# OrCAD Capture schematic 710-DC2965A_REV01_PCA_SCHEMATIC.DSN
size Custom
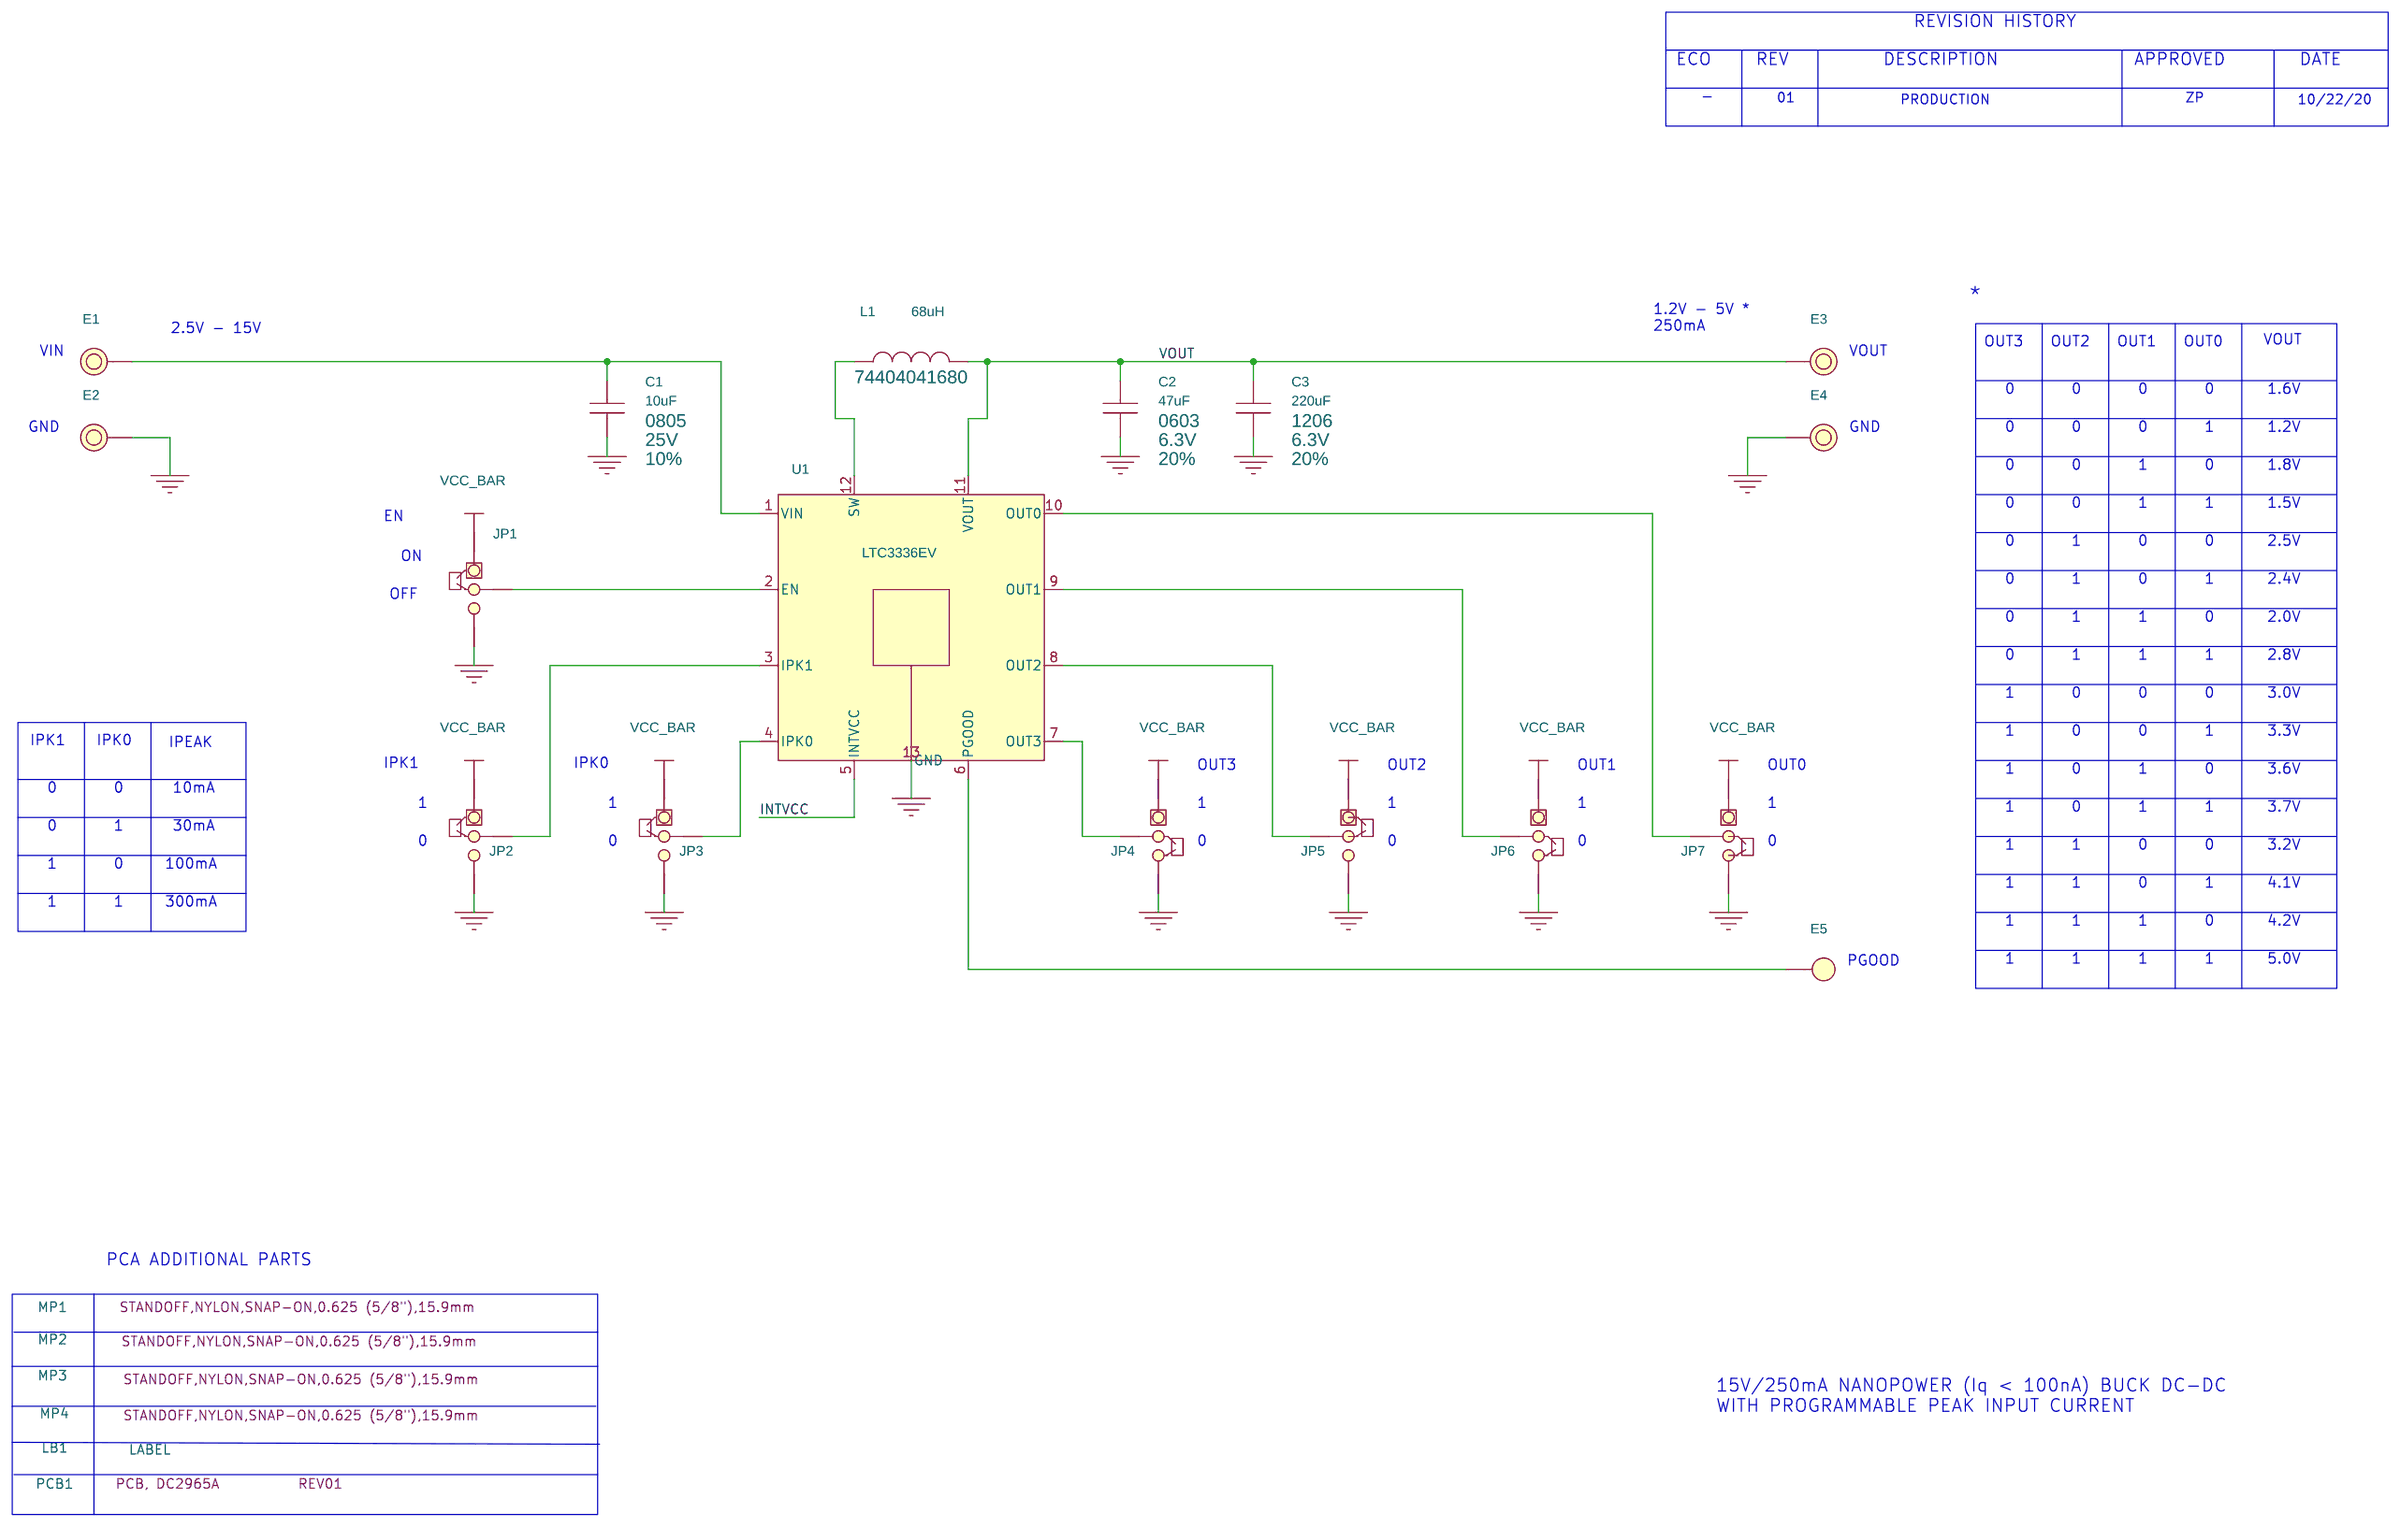
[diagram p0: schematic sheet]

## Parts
C1  10uF  [CC0805N]
C2  47uF  [CC0603N]
C3  220uF  [CC1206N]
E1  TEST POINT  [MILLMAX2501]
E2  TEST POINT  [MILLMAX2501]
E3  TEST POINT  [MILLMAX2501]
E4  TEST POINT  [MILLMAX2501]
E5  TEST POINT  [MILLMAX2308]
JP1  HDR  [HD1X3-079]
JP2  HDR  [HD1X3-079]
JP3  HDR  [HD1X3-079]
JP4  HDR  [HD1X3-079]
JP5  HDR  [HD1X3-079]
JP6  HDR  [HD1X3-079]
JP7  HDR  [HD1X3-079]
L1  68uH  [WURTH-74404041680]
LB1  LABEL  [895-0154_REV01]
MP1  STANDOFF  [KEYSTONE_8829-8834]
MP2  STANDOFF  [KEYSTONE_8829-8834]
MP3  STANDOFF  [KEYSTONE_8829-8834]
MP4  STANDOFF  [KEYSTONE_8829-8834]
PCB1  PCB, DC2965A
U1  LTC3336EV  [LTC-LQFN-12-1530]
XJP1  SHUNT
XJP2  SHUNT
XJP3  SHUNT
XJP4  SHUNT
XJP5  SHUNT
XJP6  SHUNT
XJP7  SHUNT

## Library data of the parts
C1 = CAP: CAP.,10uF,X5R,25V,10%,0805; CLASS: DISCRETE; Dielectric Type: X5R; FPLIST: CC0805N,CC0805L,CC0805M; Inventory Qty: 17285; Manufacturer: AVX; Manufacturer PN: 08053D106KAT2A; PART_NUMBER: 150-3405; Package Size: 0805; Package Type: SMD; Rated Voltage: 25V; Tolerance: 10%
C2 = CAP: CAP.,47uF,X5R,6.3V,20%,0603,NO SUBS. ALLOWED; CLASS: DISCRETE; Dielectric Type: X5R; FPLIST: CC0603N,CC0603L,CC0603M; Inventory Qty: 7581; Manufacturer: MURATA; Manufacturer PN: GRM188R60J476ME15D; PART_NUMBER: 150-2392; Package Size: 0603; Package Type: Surface Mount, MLCC; Rated Voltage: 6.3V; Temperature Coefficient: X5R; Tolerance: 20%
C3 = CAP: CAP.,220uF,X5R,6.3V,20%,1206; CLASS: DISCRETE; Dielectric Type: X5R; FPLIST: CC1206N,CC1206L,CC1206M; Inventory Qty: 0; Manufacturer: MURATA; Manufacturer PN: GRM31CR60J227ME11L; PART_NUMBER: 150-3559; Package Size: 1206; Rated Voltage: 6.3V; Tolerance: 20%
E1-E4 = TESTPOINT_.219_MILL-MAX_2501: TEST POINT,TURRET,0.094" MTG. HOLE,PCB 0.062" THK; CLASS: IO; Inventory Qty: 823526; Manufacturer: MILL-MAX; Manufacturer PN: 2501-2-00-80-00-00-07-0; PART_NUMBER: 260-0003
E5 = TEST_POINT_.156_MILL-MAX_2308: TEST POINT,TURRET,0.064" MTG. HOLE,PCB 0.062" THK; CLASS: IO; Inventory Qty: 1142083; Manufacturer: MILL-MAX; Manufacturer PN: 2308-2-00-80-00-00-07-0; PART_NUMBER: 260-0004
JP1-JP7 = 1X3_C: CONN.,HDR,MALE,1x3,2mm,VERT,ST,THT,NO SUBS. ALLOWED; CLASS: IO; Inventory Qty: 28997; Manufacturer: Wurth Elektronik; Manufacturer PN: 62000311121; PART_NUMBER: 250-0639
L1 = IND_ALT: FIXED IND 68UH 450MA 1.495 OHM; CLASS: DISCRETE; Manufacturer: Wurth Electronics Inc.; Manufacturer PN: 74404041680; PART_NUMBER: TMP-4449; Package Size: Nonstandard; Tolerance: 20%
LB1 = BLANK_LABEL: LABEL SPEC, DEMO BOARD SERIAL NUMBER; Inventory Qty: 0; Manufacturer: BRADY; Manufacturer PN: THT-96-717-10; PART_NUMBER: 895-0154
MP1-MP4 = BLANK_PINLESS_MECHANICAL_PART: STANDOFF,NYLON,SNAP-ON,0.625 (5/8"),15.9mm; CLASS: DISCRETE; Inventory Qty: 185253; Manufacturer: KEYSTONE; Manufacturer PN: 8834; PART_NUMBER: 763-0013
PCB1 = BLANK_PCB_PART: BOM Notes: REV01; CLASS: DISCRETE; Inventory Qty: 0; Manufacturer: PHASE 3 TECHNOLOGIES INC.; Manufacturer PN: 600-DC2965A; PART_NUMBER: TMP-4476
U1 = LTC3336EV: 15V/250mA Nanopower Buck DC-DC with Programmable Peak Input Current; CLASS: IC; Inventory Qty: 0; Manufacturer: ANALOG DEVICES, INC.; Manufacturer PN: LTC3336EV#PBF; PART_NUMBER: TMP-6999; Package Size: 2mm x 2mm x 0.74mm; Package Type: LQFN-12
XJP1-XJP7 = SHUNT_2MM_D: CONN.,SHUNT,FEMALE,2 POS,2mm; CLASS: IO; Inventory Qty: 64675; Manufacturer: Wurth Elektronik; Manufacturer PN: 60800213421; PART_NUMBER: 250-0485

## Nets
GND: C1.2 C2.2 C3.2 E2.1 E4.1 JP1.3 JP2.3 JP3.3 JP4.3 JP5.3 JP6.3 JP7.3 U1.13(GND)
INTVCC: JP1.1 JP2.1 JP3.1 U1.5(INTVCC)
VOUT: C2.1 C3.1 E3.1 JP4.1 JP5.1 JP6.1 JP7.1 L1.2 U1.11(VOUT)
N17680325: JP1.2 U1.2(EN)
N17681047: JP2.2 U1.3(IPK1)
N17681190: JP3.2 U1.4(IPK0)
N17681344: E5.1(A) U1.6(PGOOD)
N17683489: JP4.2 U1.7(OUT3)
N17683501: JP5.2 U1.8(OUT2)
N17683517: JP6.2 U1.9(OUT1)
N17683529: JP7.2 U1.10(OUT0)
N17683790: C1.1 E1.1 U1.1(VIN)
N17693979: L1.1 U1.12(SW)

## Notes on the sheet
- REVISION HISTORY
- ECO
- REV
- DESCRIPTION
- APPROVED
- DATE
- -
- 01
- PRODUCTION
- ZP
- 10/22/20
- *
- 2.5V - 15V
- 1.2V - 5V *
  250mA
- VIN
- VOUT
- OUT3
- OUT2
- OUT1
- OUT0
- VOUT
- 0
- 0
- 0
- 0
- 1.6V
- GND
- GND
- 0
- 0
- 0
- 1
- 1.2V
- 0
- 0
- 1
- 0
- 1.8V
- 0
- 0
- 1
- 1
- 1.5V
- EN
- 0
- 1
- 0
- 0
- 2.5V
- ON
- OFF
- 0
- 1
- 0
- 1
- 2.4V
- 0
- 1
- 1
- 0
- 2.0V
- 0
- 1
- 1
- 1
- 2.8V
- 1
- 0
- 0
- 0
- 3.0V
- 1
- 0
- 0
- 1
- 3.3V
- IPK1
- IPK0
- IPEAK
- IPK1
- IPK0
- OUT3
- OUT2
- OUT1
- OUT0
- 1
- 0
- 1
- 0
- 3.6V
- 0
- 0
- 10mA
- 1
- 1
- 1
- 1
- 1
- 1
- 1
- 0
- 1
- 1
- 3.7V
- 0
- 1
- 30mA
- 0
- 0
- 0
- 0
- 0
- 0
- 1
- 0
- 100mA
- 1
- 1
- 0
- 0
- 3.2V
- 1
- 1
- 0
- 1
- 4.1V
- 1
- 1
- 300mA
- 1
- 1
- 1
- 0
- 4.2V
- PGOOD
- 1
- 1
- 1
- 1
- 5.0V
- PCA ADDITIONAL PARTS
- 15V/250mA NANOPOWER (Iq < 100nA) BUCK DC-DC
  WITH PROGRAMMABLE PEAK INPUT CURRENT
